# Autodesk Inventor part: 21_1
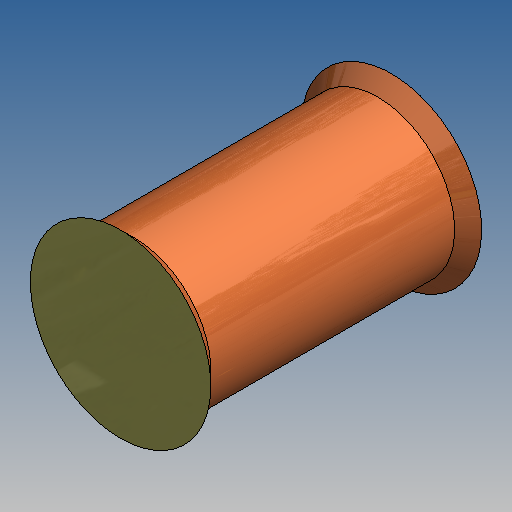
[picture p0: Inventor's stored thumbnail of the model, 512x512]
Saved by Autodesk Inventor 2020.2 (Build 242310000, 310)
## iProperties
Part Number: 21_1
Material: Generic
Document SubType Name: Modeling
Designer: amoles
Appearance: Default
Author: amoles
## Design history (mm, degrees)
feature "Base1"
body "Solid1"
